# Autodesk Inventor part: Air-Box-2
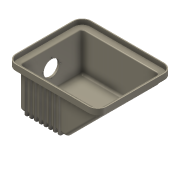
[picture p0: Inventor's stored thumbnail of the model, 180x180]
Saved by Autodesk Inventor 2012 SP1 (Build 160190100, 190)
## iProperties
Shininess: 64.0
Length Units: 11269
Angle Units: 11279
Time Units: 11290
Mass Units: 11283
Length Display Precision: 3
Angle Display Precision: 2
Compacted: True
Part Number: Air-Box-2
Document SubType Name: Modeling
Created: 2004-03
Designer: Administrator
Manufacturer: Standard
Standards Organization: Custom
Density: 1 g/cm^3
Material: Default
Density: 0.0
Volumn: 0.0
Area: 0.0
PropertySet Name: Model Information
Control State: 0
Master: False
Checked Out: False
Author: Administrator
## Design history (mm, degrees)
sketch "Sketch1"
  geometry: L1 (0, 0)-(250, 0); L2 (250, 0)-(250, 200); L3 (250, 200)-(0, 200); L4 (0, 200)-(0, 0)
  constraints: 8 end point, 2 parallel, 1 horizontal, 1 perpendicular
  dimensions: "d0" = 200 distance of L3.end L1.start; "d1" = 250 distance of L2.end L3.end
extrude "Extrusion1" new body sketch "Sketch1" distance "d2" = 25; taper "d3" = 0 deg
workplane "Work Plane1"
sketch "Sketch2"
  geometry: L1 (0, -25)-(0, -125); L2 (0, -125)-(150, -125); L3 (150, -125)-(250, -25); L4 (0, -25)-(250, -25)
  constraints: 8 end point, 1 parallel, 1 perpendicular, 1 vertical
  dimensions: "d4" = 100 distance of L1.start L1.end; "d5" = 150 distance of L1.end L2.end (derived); "d7" = 45 deg angle of L3 L2
extrude "Extrusion2" join sketch "Sketch2" stored distance "d8" = 200 (= d0); taper "d9" = 0 deg
fillet "Fillet1" dims "d10" = 10
shell "Shell1" dims "d11" = 3
sketch "Sketch3"
  geometry: L1 (10, 0)-(240, 0) reference; L2 (250, 10)-(250, 190) reference; L3 (240, 200)-(10, 200) reference; L4 (0, 190)-(0, 10) reference; L5 (10, -20)-(240, -20); L6 (270, 10)-(270, 190); L7 (240, 220)-(10, 220); L8 (-20, 190)-(-20, 10); A1 r 10 centre (10, 10) between (0, 10) and (10, 0) reference; A2 r 10 centre (240, 10) between (240, 0) and (250, 10) reference; A3 r 10 centre (240, 190) between (250, 190) and (240, 200) reference; A4 r 10 centre (10, 190) between (10, 200) and (0, 190) reference; A5 r 30 centre (10, 10) between (-20, 10) and (10, -20); A6 r 30 centre (240, 10) between (240, -20) and (270, 10); A7 r 30 centre (240, 190) between (270, 190) and (240, 220); A8 r 30 centre (10, 190) between (10, 220) and (-20, 190)
  constraints: 8 end point, 8 point on circle, 4 centre point, 7 other
  dimensions: "d12" = 20 distance between parallel lines of L8 L4
extrude "Extrusion3" join sketch "Sketch3" distance "d13" = 3 (= d11); taper "d14" = 0 deg
sketch "Sketch4"
  geometry: L1 (10, -20)-(240, -20) reference; L2 (270, 10)-(270, 190) reference; L3 (240, 220)-(10, 220) reference; L4 (-20, 190)-(-20, 10) reference; L5 (10, -17)-(240, -17); L6 (267, 10)-(267, 190); L7 (240, 217)-(10, 217); L8 (-17, 190)-(-17, 10); A1 r 30 centre (10, 10) between (-20, 10) and (10, -20) reference; A2 r 30 centre (240, 10) between (240, -20) and (270, 10) reference; A3 r 30 centre (240, 190) between (270, 190) and (240, 220) reference; A4 r 30 centre (10, 190) between (10, 220) and (-20, 190) reference; A5 r 27 centre (10, 10) between (-17, 10) and (10, -17); A6 r 27 centre (240, 10) between (240, -17) and (267, 10); A7 r 27 centre (240, 190) between (267, 190) and (240, 217); A8 r 27 centre (10, 190) between (10, 217) and (-17, 190)
  constraints: 8 end point, 8 point on circle, 4 centre point, 7 other
  dimensions: "d15" = 3 distance between parallel lines of L4 L8 (= d11)
extrude "Extrusion4" join sketch "Sketch4" distance "d16" = 15; taper "d17" = 0 deg
sketch "Sketch5"
  geometry: L1 (0, 180)-(112, 180) reference; L2 (0, 0)-(0, 180) reference; C1 r 32.5 at (56, 90); 2 further points
  constraints: 2 midpoint, 1 centre point, 1 horizontal alignment, 1 vertical alignment
  dimensions: "d18" = 65 diameter of C1
extrude "Extrusion5" join sketch "Sketch5" distance "d19" = 3; taper "d20" = 0 deg
sketch "Sketch6"
  geometry: C1 r 32.5 at (0, 0) reference
hole "Hole1" sketch "Sketch6" at (0, 0) diameter "d21" = 50; stored, may be unused: countersink angle "d25" = 82 deg, drill point angle "d27" = 118 deg; dims "d22" = 6, "d23" = 4, "d24" = 2, "d26" = 6
fillet "Fillet2" dims "d28" = 3
fillet "Fillet3" dims "d29" = 6
sketch "Sketch7"
  geometry: L1 (0, 0)-(42.821, 0); C1 r 25 at (0, 0) reference; C2 r 32.5 at (0, 0) reference; 1 further point
  constraints: 2 end point, 1 horizontal, 1 point on line
  dimensions: "d30" = 28.75 distance of point (28.75, 0) C1.centre
hole "Hole2" sketch "Sketch7" at (28.75, 0) diameter "d31" = 4.134; stored, may be unused: countersink angle "d35" = 82 deg, drill point angle "d37" = 118 deg; dims "d32" = 6, "d33" = 4, "d34" = 2, "d36" = 6
pattern_circular "Circular Pattern1" dims angle "d40" = 360 deg
workplane "Work Plane2"
sketch "Sketch8" dims "d48" = 10
  geometry: L1 (135.858, 16)-(-94.142, 16) reference; L2 (-94.142, -196)-(135.858, -196) reference; L3 (0, 0)-(135.858, 0) reference; L4 (135.858, -180)-(0, -180) reference; L5 (120.858, 16)-(120.858, -196); L6 (105.858, 16)-(105.858, -196); L7 (90.858, 16)-(90.858, -196); L8 (75.858, 16)-(75.858, -196); L9 (60.858, 16)-(60.858, -196); L10 (45.858, 16)-(45.858, -196); L11 (30.858, 16)-(30.858, -196); L12 (15.858, 16)-(15.858, -196)
  constraints: 16 end point, 2 point on line, 1 horizontal, 1 perpendicular, 21 other
  dimensions: "d42" = 15 distance from line of L1.start L5; "d45" = 15 distance of L5.start L6.start
feature "Rib1" sketch "Sketch8" dims "d50" = 3, "d51" = 1
fillet "Fillet4" dims "d52" = 10
body "Solid1"
other parameters: "d41" = 5
